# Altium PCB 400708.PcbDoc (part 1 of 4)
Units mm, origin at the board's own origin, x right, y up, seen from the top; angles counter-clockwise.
Board outline 117 x 63.5 mm, 4 copper layers (Top Layer, Mid-Layer 1, Mid-Layer 2, Bottom Layer), stack 1.556 mm thick; 207 components, 162 nets, 822 pads, 1266 vias.
Unrouted connection lines stored in the file: 43.
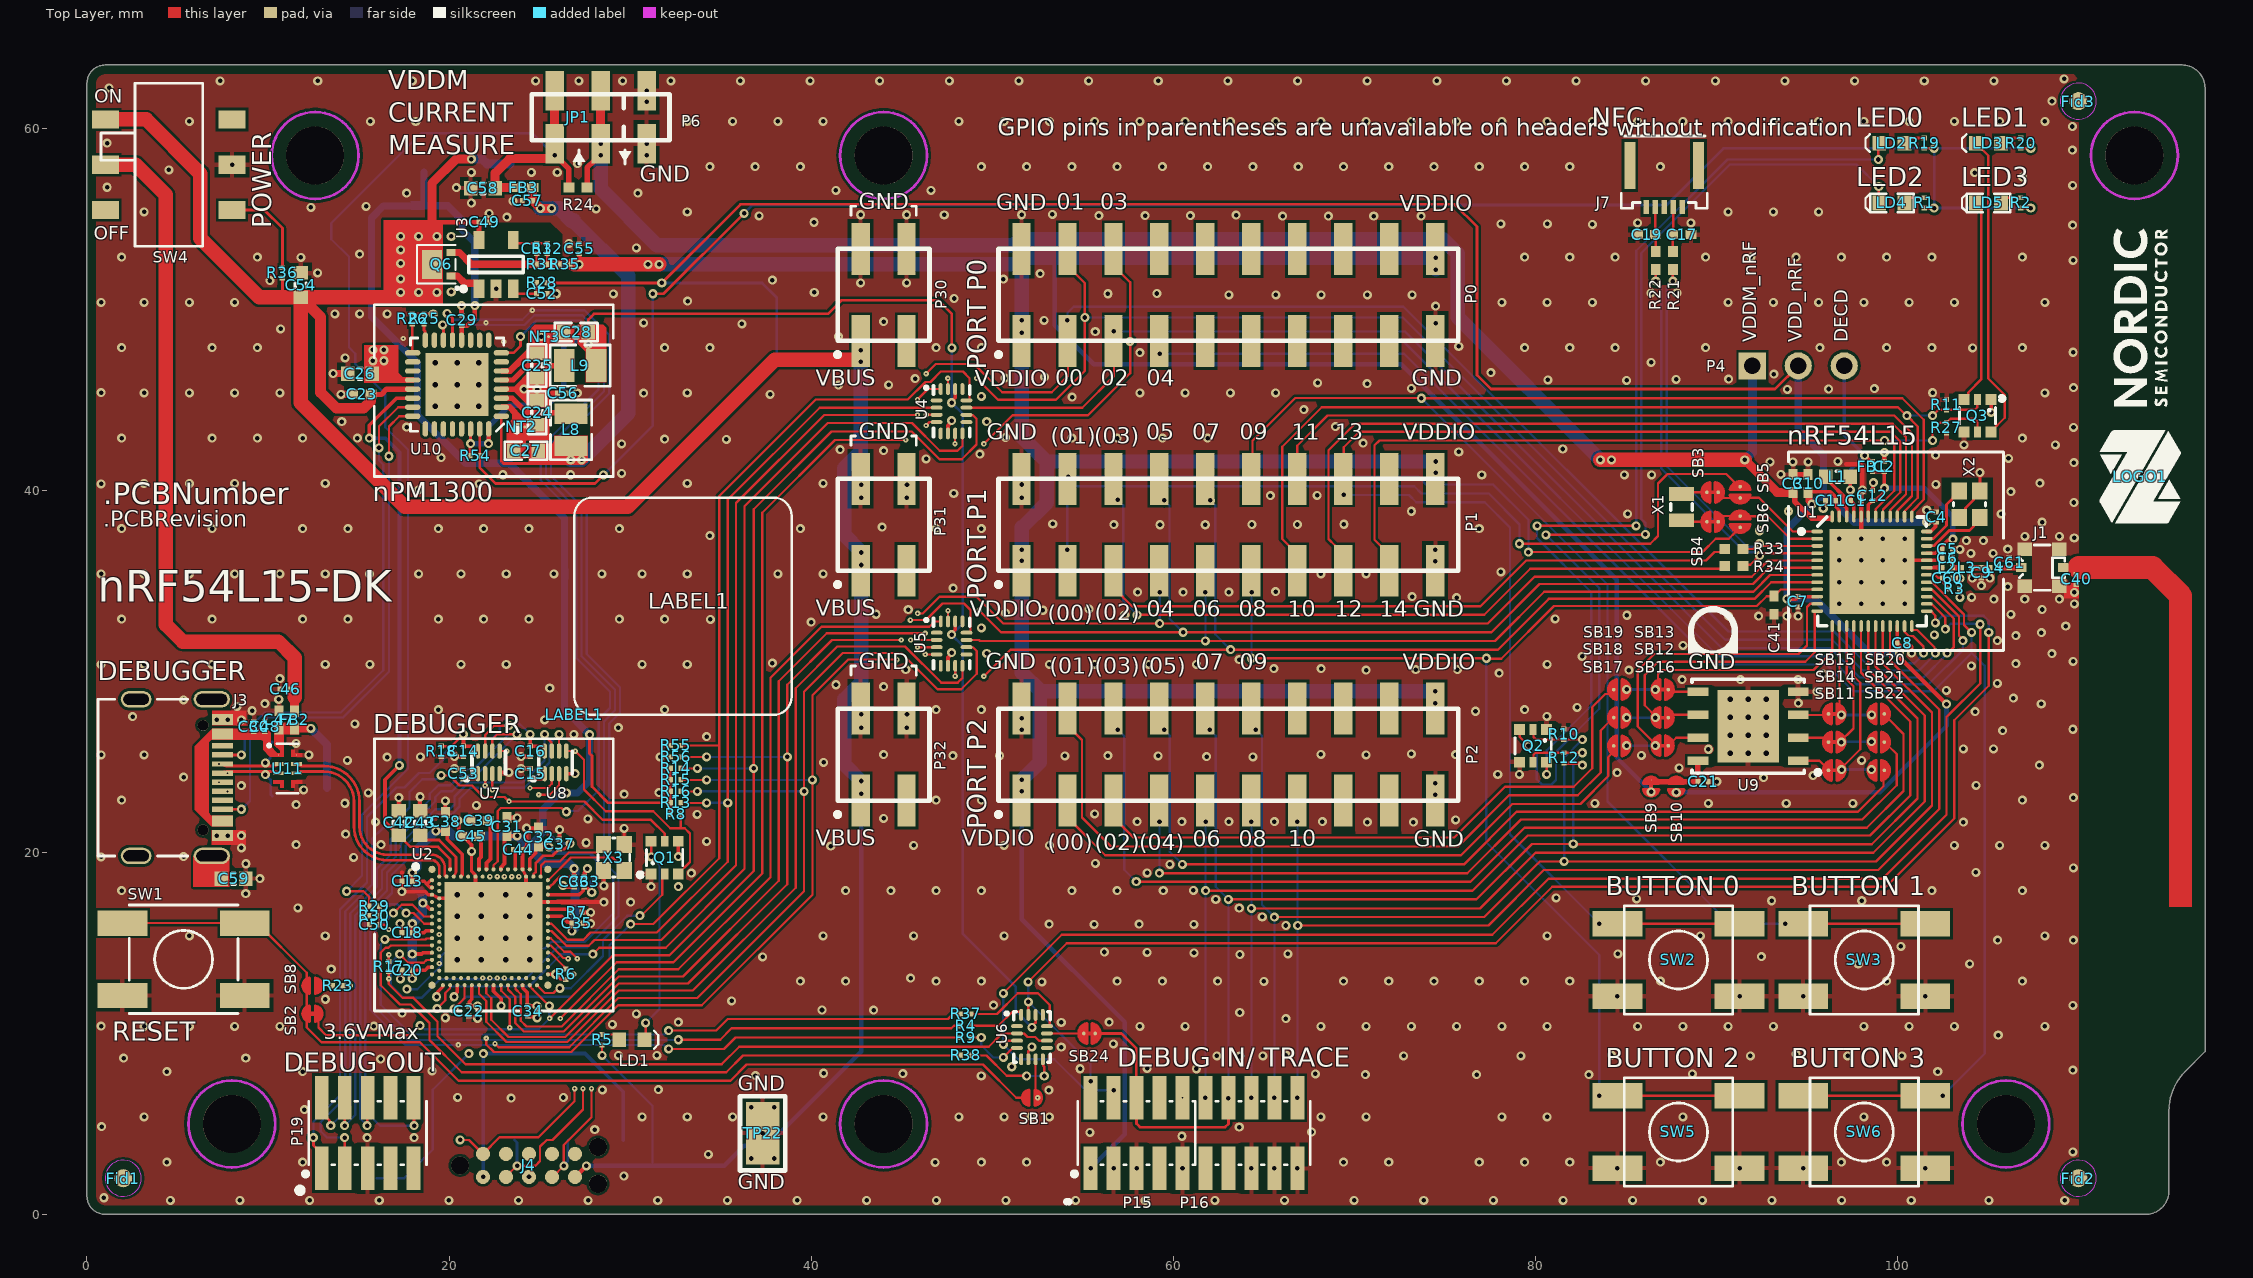
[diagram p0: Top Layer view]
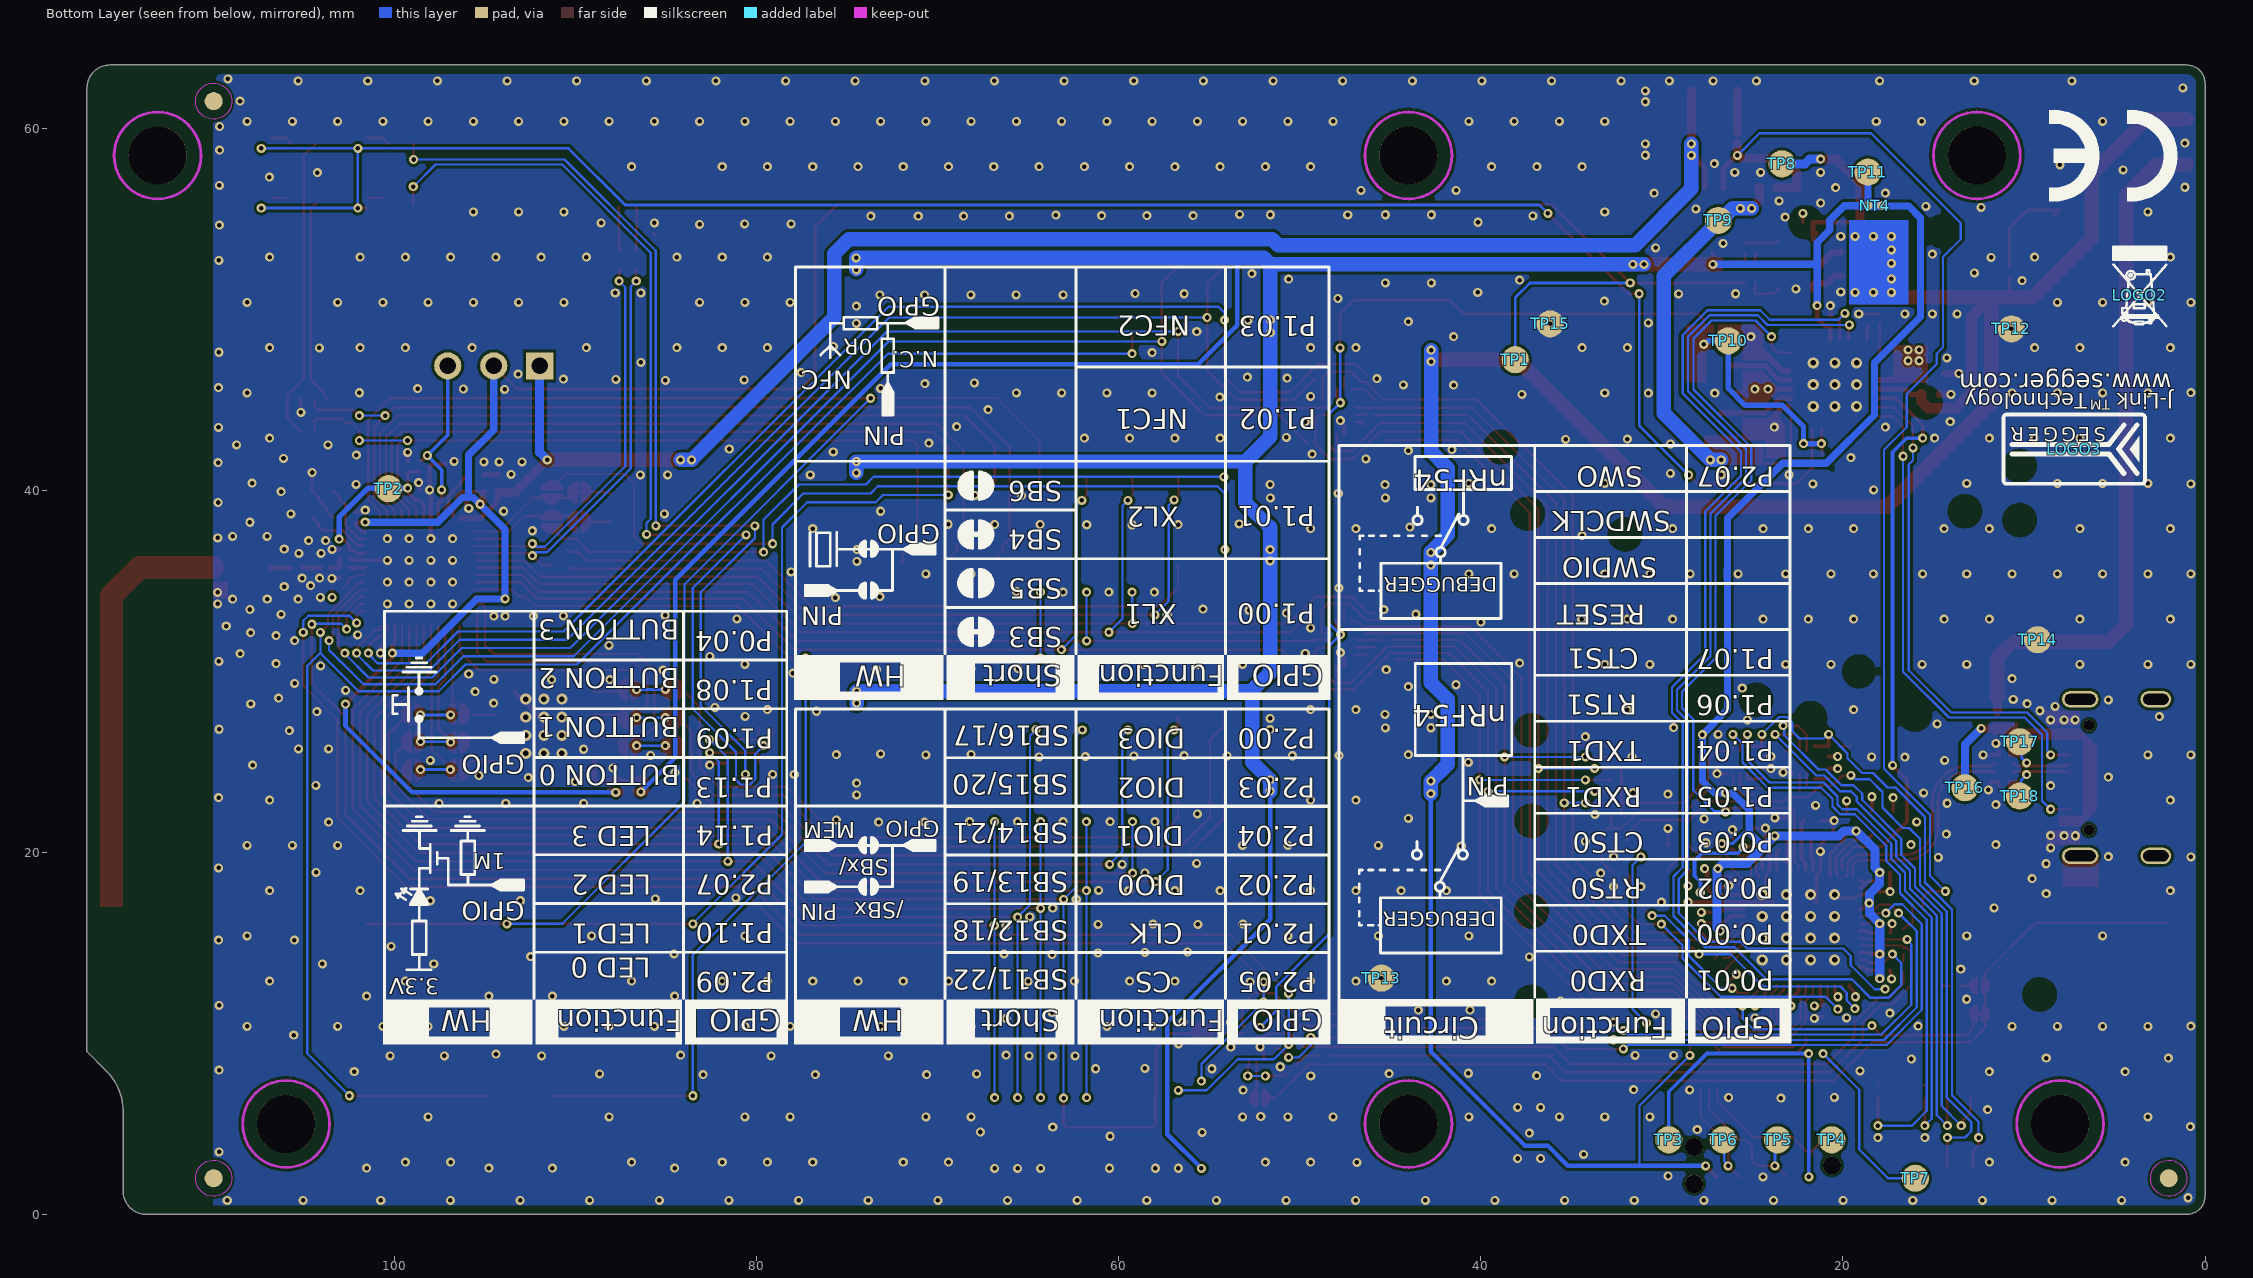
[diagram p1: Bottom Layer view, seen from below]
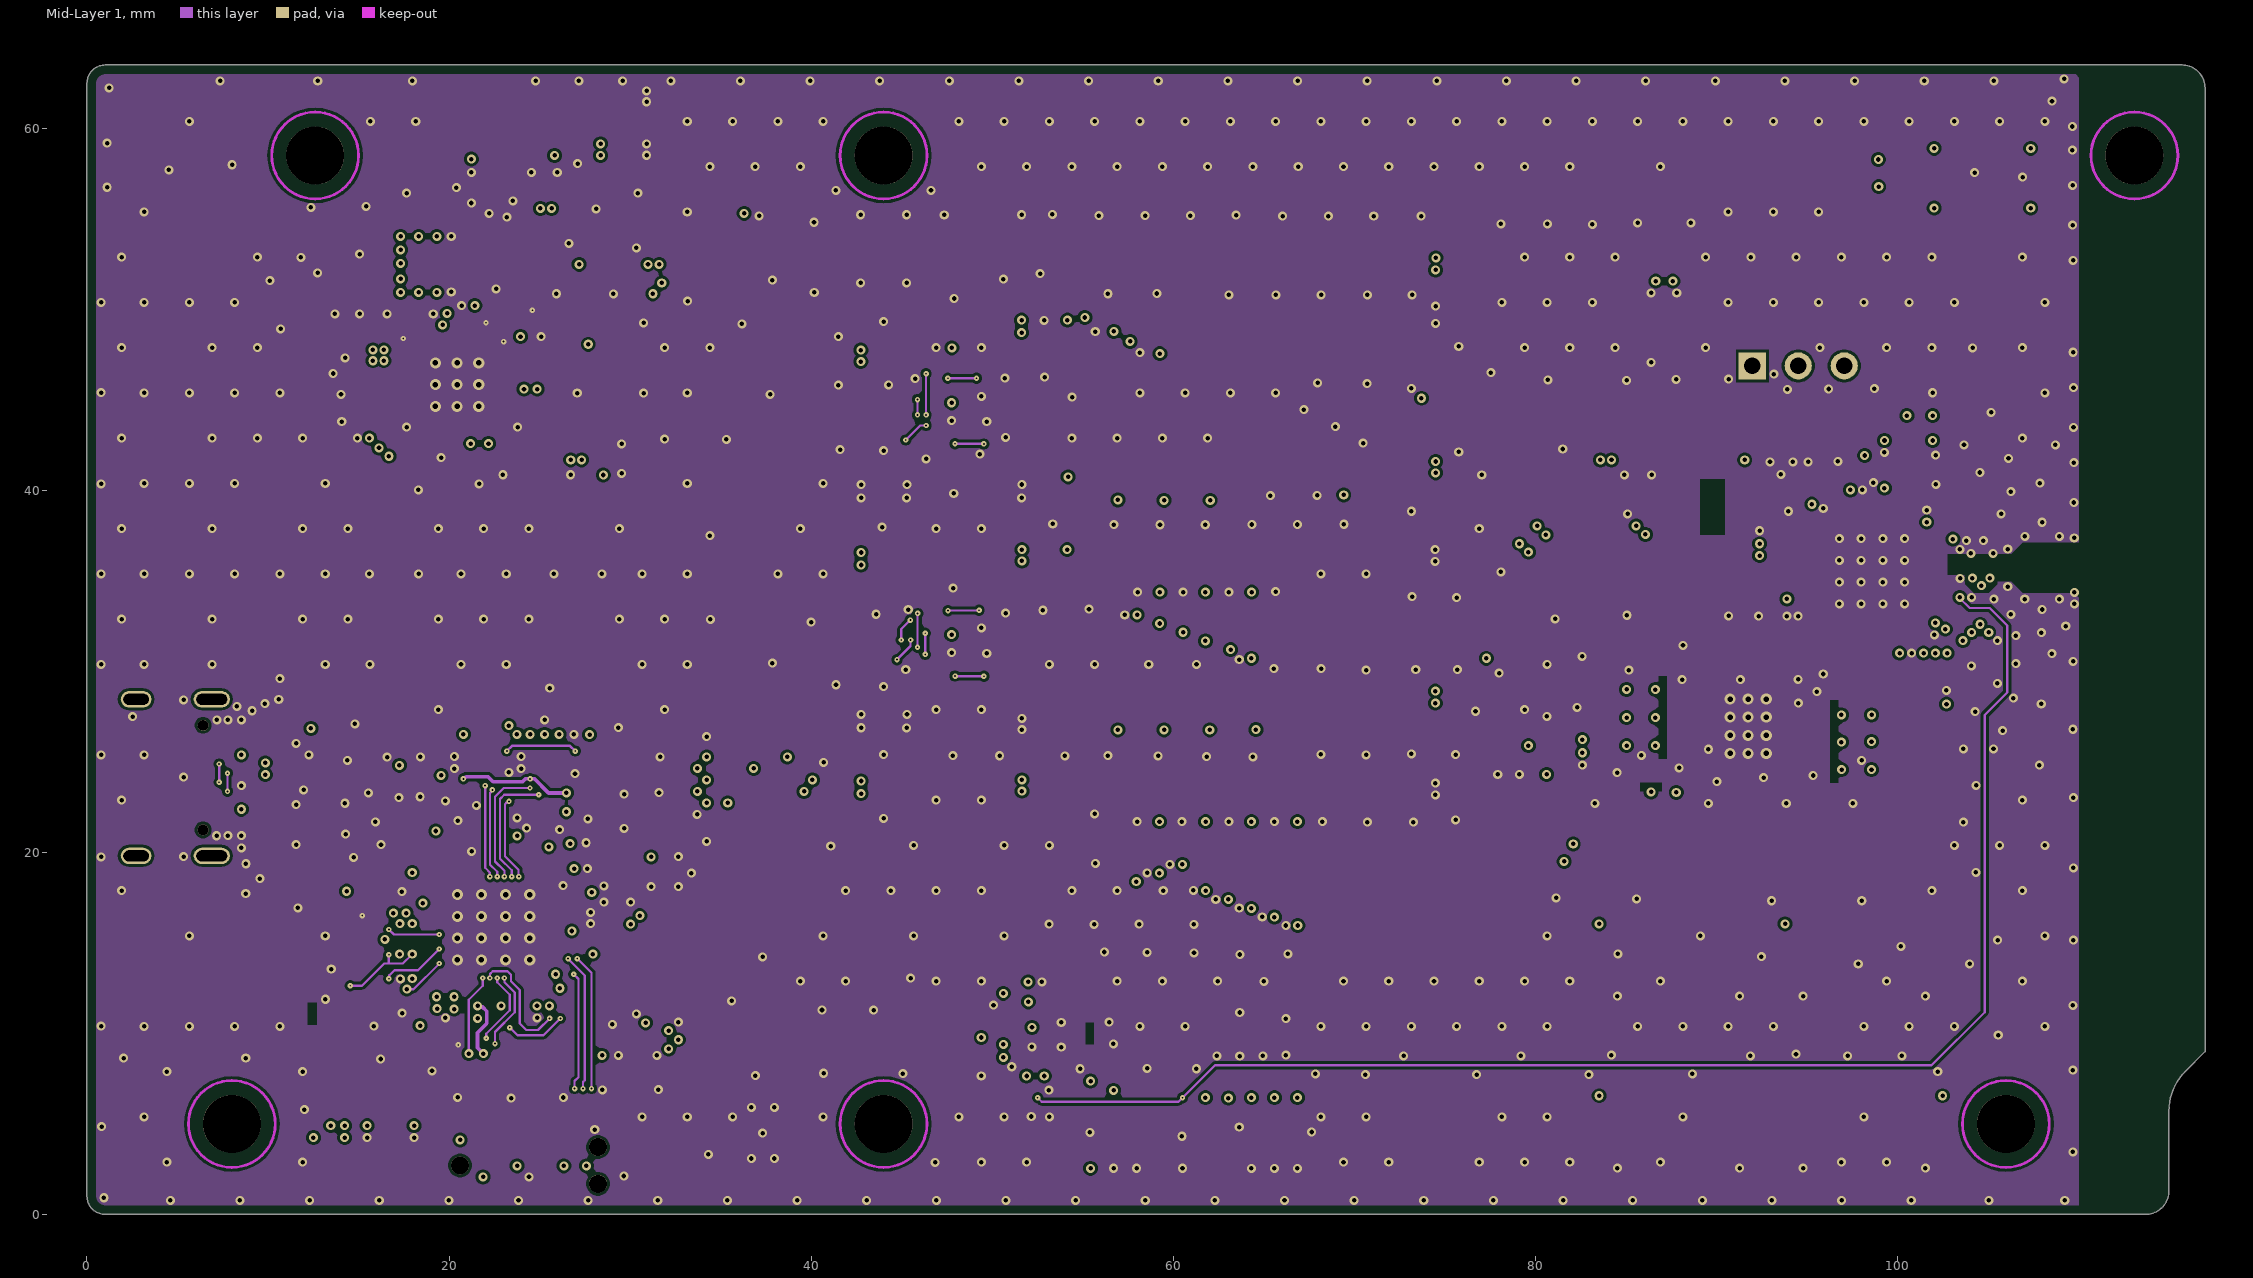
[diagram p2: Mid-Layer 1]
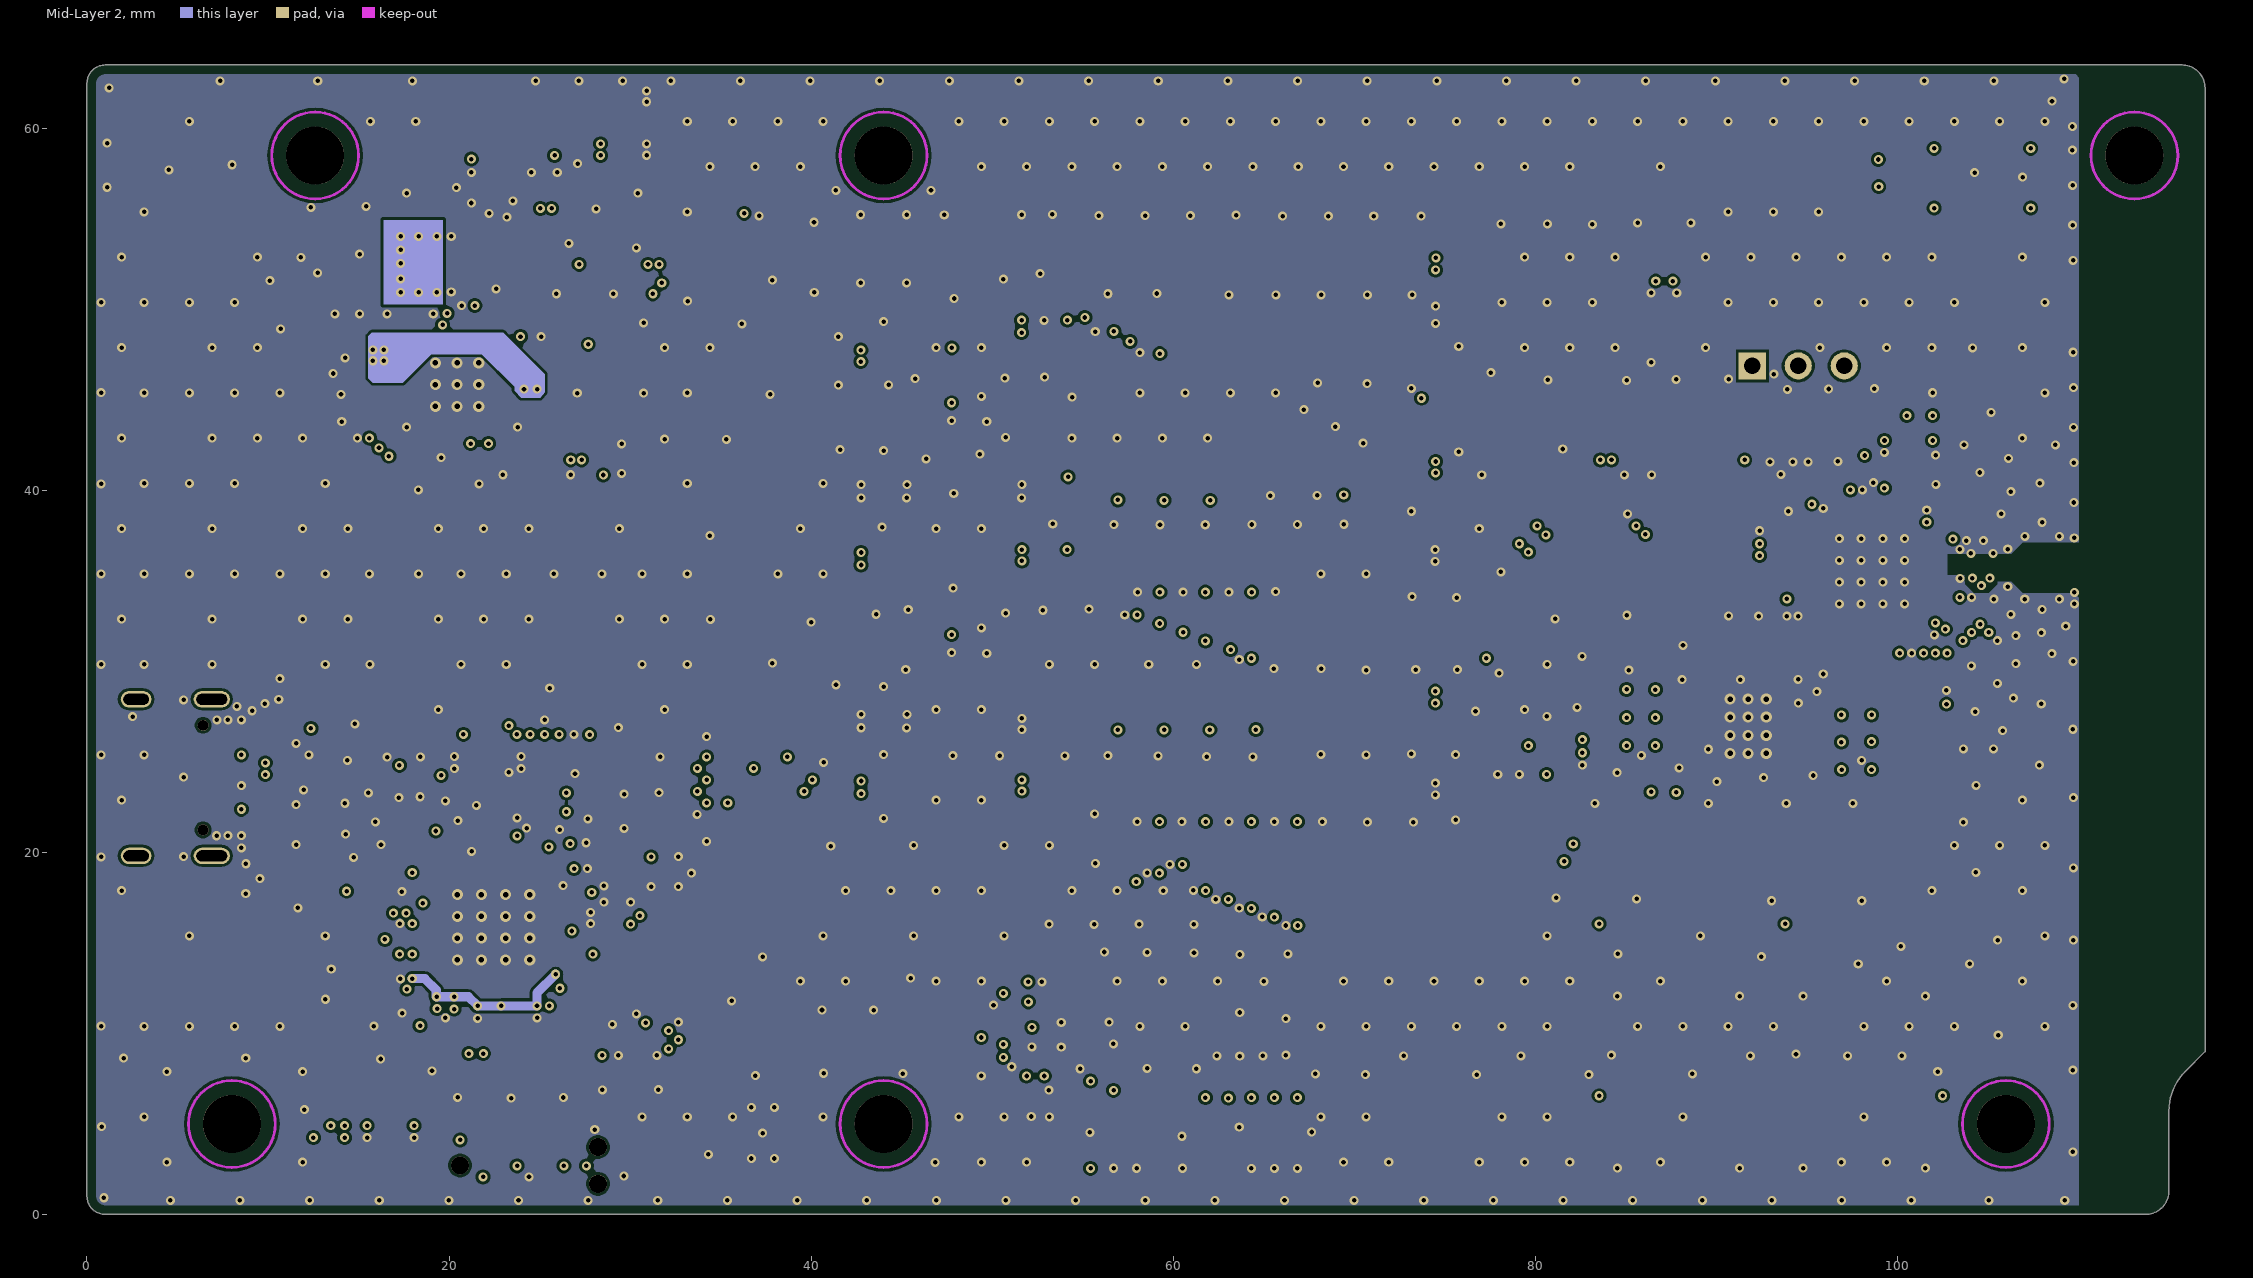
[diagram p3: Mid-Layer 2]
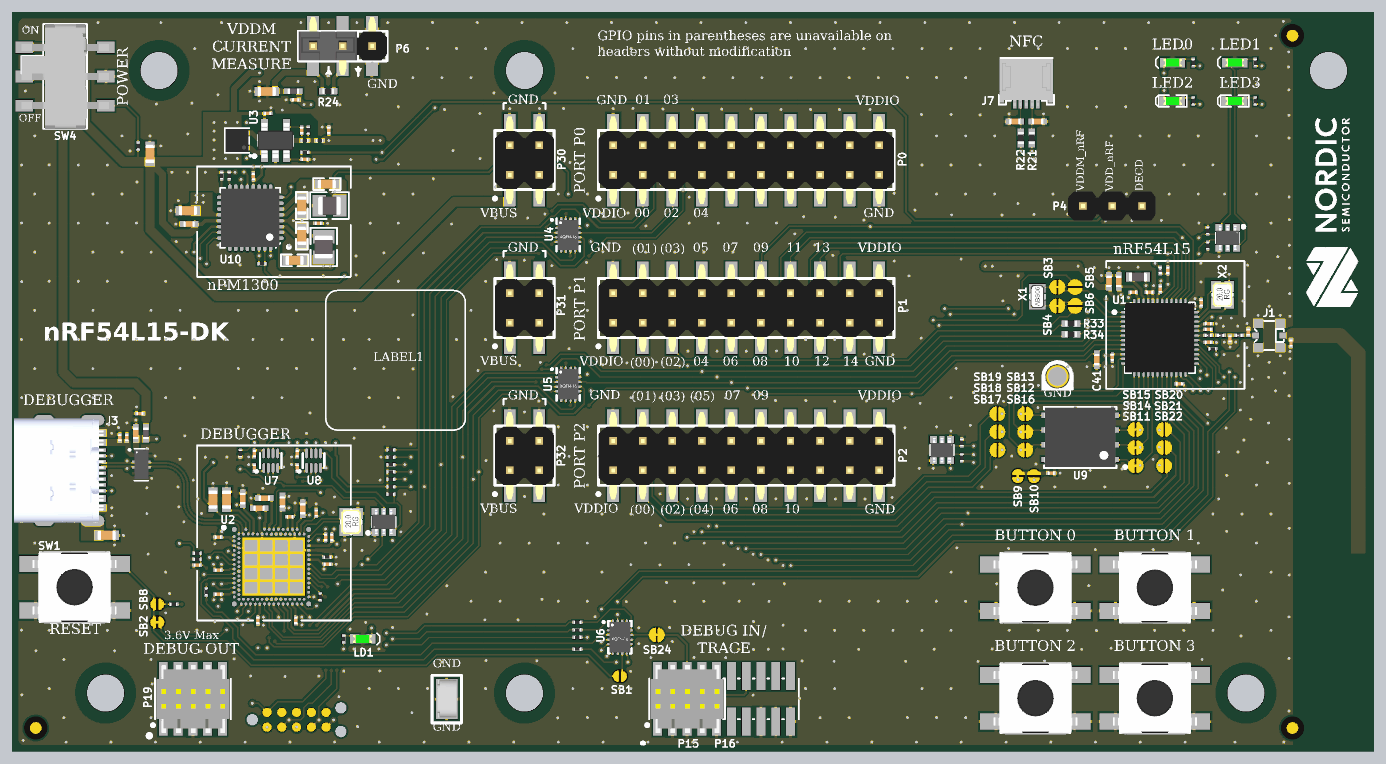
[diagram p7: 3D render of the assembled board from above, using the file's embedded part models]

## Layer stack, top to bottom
Top Solder: solder mask 0.0102, Solder Resist, Dk 3.5
Top Layer: signal copper 0.048
Dielectric 1: prepreg 0.1, PP-021, Dk 4.2
Mid-Layer 1: signal copper 0.03
Dielectric 2: core 1.2, Core-042, Dk 4.2
Mid-Layer 2: signal copper 0.03
Dielectric 3: prepreg 0.1, PP-021, Dk 4.2
Bottom Layer: signal copper 0.048
Bottom Solder: solder mask 0.0102, Solder Resist, Dk 3.5

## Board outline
1.016,0 cw(c1.016,1.016) 0,1.016 0,62.484 cw(c1.016,62.484) 1.016,63.5 115.734,63.5 cw(c115.734,62.23) 117.004,62.23 117.004,9 115.92,7.916 ccw(c118.132,5.705) 115.004,5.705 115.004,1.295 cw(c113.709,1.295) 113.709,0

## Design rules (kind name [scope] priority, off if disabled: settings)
AssemblyTestPointUsage [All] p1 off:
AssemblyTestpoint [All] p1 off: testpointundercomponent=TRUE minsize=1.016 maxsize=2.54 preferedsize=1.524 minholesize=0 maxholesize=1.016 preferedholesize=0.813 testpointgrid=0.025 usegrid=TRUE gridtolerance=0 allowsidetop=TRUE allowsidebottom=TRUE
BoardOutlineClearance [All] p1: gap=0.508 ignorepadtopadclearanceinfootprint=FALSE except(0: Arc-SplitContinuation Track-SplitContinuation SMDPad-SplitContinuation THPad-SplitContinuation Via-SplitContinuation Fill-SplitContinuation Poly-SplitContinuation Region-SplitContinuation Text-SplitContinuation)
Clearance ANT_Clearance [InNet('ANT') or InNet('RF') or InNet('NetC9_2') or InNet('NetC6_2')] p1: gap=0.16 ignorepadtopadclearanceinfootprint=FALSE
Clearance Polygon_Clearance [(InNamedPolygon('Mid_Layer1-GND')) or (InNamedPolygon('Bottom_Layer-GND')) or (InNamedPolygon('Mid_Layer2-GND')) or (InNamedPolygon('Top_Layer-GND'))] p2: gap=0.15 ignorepadtopadclearanceinfootprint=FALSE
Clearance Clearance_IMCU [WithinRoom('nRF5340')] p3: gap=0.1 ignorepadtopadclearanceinfootprint=FALSE
Clearance DiffPair_Clearance [InNetClass('IMCU_USB')] p4: gap=0.127 ignorepadtopadclearanceinfootprint=FALSE
Clearance [All] p5: gap=0.15 ignorepadtopadclearanceinfootprint=FALSE except(0.25: THPad-Region)
ComponentClearance [All] p1 off: gap=0.254 collisioncheckmode=3 verticalgap=0.254 showdistances=FALSE
DiffPairsRouting [InDifferentialPairClass('All Differential Pairs')] p1: maxlimit=0.15 minlimit=0.15 mostfreqgap=0.15 toplayer_minwidth=0.125 toplayer_maxwidth=0.153 toplayer_prefwidth=0.153 midlayer1_minwidth=0.125 midlayer1_maxwidth=0.153 midlayer1_prefwidth=0.125 midlayer4_minwidth=0.125 midlayer4_maxwidth=0.153 midlayer4_prefwidth=0.125 bottomlayer_minwidth=0.125 bottomlayer_maxwidth=0.153 bottomlayer_prefwidth=0.153 maxuncoupledlength=10
FabricationTestPointUsage TestPointUsage [All] p1 off: valid=2 allowmultiple=FALSE
FabricationTestpoint Testpoint [All] p1 off: side=2 testpointundercomponent=TRUE minsize=1.016 maxsize=2.54 preferedsize=1.524 minholesize=0 maxholesize=1.016 preferedholesize=0.813 testpointgrid=2.54 allowsidebottom=TRUE usegrid=TRUE gridtolerance=0
Height [All] p1 off: minheight=0 maxheight=25.4 prefheight=12.7
HoleSize [All] p1: absolutevalues=TRUE maxlimit=5 minlimit=0.1 maxpercent=80.000 minpercent=20.000
HoleToHoleClearance [IsThruVia] p1: gap=0.35 allowstackedmicrovias=FALSE
LayerPairs [All] p1 off: enforce=TRUE
MatchedLengths "Schematic Matched Net Lengths" [InNetClass('TRACE')] p1: tolerance=25.4 checknetsindiffpair=FALSE checkdiffpairvsdiffpair=TRUE checkxsignals=TRUE checkothers=TRUE usedelayunits=TRUE delaytolerance=500.000000
MatchedLengths MatchedLengths-Diffpairs [InDifferentialPairClass('All Differential Pairs')] p2: tolerance=1.27 checknetsindiffpair=TRUE checkdiffpairvsdiffpair=FALSE checkxsignals=FALSE checkothers=FALSE
MinimumAnnularRing [All] p1 off: minimumring=0.1
MinimumSolderMaskSliver [All] p1: minsoldermaskwidth=0.1
NetAntennae [All] p1 off: netantennaetolerance=0.3
PolygonConnect PolygonConnect_TP [HasFootprint('TP_SMD_D1.5mm') vs InNet('GND')] p1: connectstyle=Direct reliefconductorwidth=0.254 reliefentries=4 polygonreliefangle="90 Angle" airgapwidth=0.254
PolygonConnect PolygonConnect_SMT_Pads [HasFootprint('COAXIAL-SWF') or InComponent('C9') or InComponent('C61') vs InNet('GND')] p2: connectstyle=Direct reliefconductorwidth=0.254 reliefentries=4 polygonreliefangle="90 Angle" airgapwidth=0.254
PolygonConnect [All] p3: thpad.connectstyle=Relief thpad.reliefconductorwidth=0.254 thpad.reliefentries=4 thpad.polygonreliefangle="90 Angle" thpad.airgapwidth=0.2 smdpad.connectstyle=Relief smdpad.reliefconductorwidth=0.254 smdpad.reliefentries=4 smdpad.polygonreliefangle="90 Angle" smdpad.airgapwidth=0.2 via.connectstyle=Direct via.reliefconductorwidth=0.254 via.reliefentries=4 via.polygonreliefangle="90 Angle" via.airgapwidth=0.254
RoutingVias RoutingVias_Blind [IsBlindVia or IsMicroVia] p1: holewidth=0.711 width=1.27 viastyle="Through Hole" minholewidth=0.711 minwidth=1.27 maxholewidth=0.711 maxwidth=1.27 useviatemplates=TRUE viatemplateguid#1={B6F7EE11-84B8-42C4-BDC0-4B8B407402DD} viatemplatename#1=v30h10m0
RoutingVias RoutingVias_thru [IsThruVia] p2: holewidth=0.305 width=0.61 viastyle="Through Hole" minholewidth=0.305 minwidth=0.61 maxholewidth=0.711 maxwidth=1.27 useviatemplates=TRUE viatemplateguid#1={462064FF-42C7-473E-A651-561C1576AFDF} viatemplateguid#2={99171295-E844-4990-BFE5-753CC0A313CB} viatemplateguid#3={DB312F71-B2A7-4ABA-8448-376194653462} viatemplateguid#4={E2A9C569-A2DE-41A1-8420-4C4C8AB4608D} viatemplatename#1=v50h25m0mx0 viatemplatename#2=v50h25m0mx0(1) viatemplatename#3=v61h30 viatemplatename#4=v61h30m0mx0
ShortCircuit ShortCircuit_P15_P16 [InComponent('P15') vs InComponent('P16')] p1: allowed=TRUE
ShortCircuit ShortCircuit_PSS [InNet('PVSS1') or InNet('PVSS2') vs InNet('GND')] p2: allowed=TRUE
ShortCircuit [All] p3: allowed=FALSE
SilkToSilkClearance [All] p1 off: silktosilkclearance=0.254
SilkToSolderMaskClearance SilkscreenOverComponentPads [IsPad] p1 off: minsilkscreentomaskgap=0.254 clearancetoexposedcopper=TRUE
SolderMaskExpansion SolderMaskExpansion_XFDFN40 [HasFootprint('XFDFN40P180X120X40-8M')] p1: expansion=0.02 istentingtop=FALSE
SolderMaskExpansion SolderMaskExpansion_footprints [HasFootprint('UDFN65P200X200X60_HS-6N') or HasFootprint('SON50P300X80-HS-11N') or HasFootprint('US8') or HasFootprint('SON50P300X80_HS-9N') or HasFootprint('BGA25C40P5X5_200X200X50') or HasFootprint('QFN40P180X140X55-10N') or HasFootprint('DX07S016JA1R1500') or HasFootprint('AQFN40P700X700X85_HS-99N') or HasFootprint('Nordic_QFN50P500X500X90-33N')] p2: expansion=0.03 istentingtop=FALSE
SolderMaskExpansion SolderMaskExpansion_VIA [IsVia] p3: expansion=0.076 istentingtop=TRUE
SolderMaskExpansion [All] p4: expansion=0.05 istentingtop=FALSE
SupplyNets "Schematic Supply Nets_12" [InNet('P5V0')] p1: voltage=0.000
SupplyNets "Schematic Supply Nets_11" [InNet('GND')] p2: voltage=0.000
SupplyNets "Schematic Supply Nets_10" [InNet('VDDM_nRF')] p3: voltage=0.000
SupplyNets "Schematic Supply Nets_9" [InNet('VDDIO')] p4: voltage=0.000
SupplyNets "Schematic Supply Nets_8" [InNet('VDD_SWD0')] p5: voltage=0.000
SupplyNets "Schematic Supply Nets_7" [InNet('P3V3')] p6: voltage=0.000
SupplyNets "Schematic Supply Nets_6" [InNet('VDD_nRF')] p7: voltage=0.000
SupplyNets "Schematic Supply Nets_5" [InNet('VDD_DBGR')] p8: voltage=0.000
SupplyNets "Schematic Supply Nets_4" [InNet('PVSS2')] p9: voltage=0.000
SupplyNets "Schematic Supply Nets_3" [InNet('PVSS1')] p10: voltage=0.000
SupplyNets "Schematic Supply Nets_2" [InNet('VBUSOUT')] p11: voltage=0.000
SupplyNets "Schematic Supply Nets_1" [InNet('VDDM')] p12: voltage=0.000
SupplyNets "Schematic Supply Nets" [InNet('VBUS')] p13: voltage=0.000
Width Width_IMCU [OnTopLayer and HasFootprint('BGA144C35P12X12_450X420X100-A8-M3')] p1: maxlimit=2.5 minlimit=0.1 preferedwidth=0.15
Width [All] p2: maxlimit=2.5 minlimit=0.125 preferedwidth=0.15
15 further rules are at their usual default settings.

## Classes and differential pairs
differential pair class IMCU: DBGR DBGR'
net class TRACE: P2.06 P2.07 P2.08 P2.09 P2.10
net class IMCU_USB: DBGR'_N DBGR'_P DBGR_N DBGR_P
component class "Power supply": C23 C24 C25 C26 C27 C28 C29 C49 C51 C52 C55 C56 C57 C58 FB3 JP1 L8 L9 NT2 NT3 P6 Q6 R24 R25 R26 R28 R31 R32 R35 R54 TP8 TP9 TP10 TP11 TP12 TP13 TP14 TP15 U3 U10
component class "Levelshifters and switches": C14 C15 C16 C53 R8 R13 R14 R15 R16 R17 R18 R55 R56 SB24 U4 U5 U6 U7 U8
component class nRF54L15: C1 C2 C3 C4 C5 C6 C7 C8 C9 C10 C11 C12 C40 C41 C60 C61 FB1 J1 L1 L2 L3 L4 P4 R3 R33 R34 SB3 SB4 SB5 SB6 SB11 SB12 SB13 SB14 SB15 SB16 SB17 SB18 SB19 SB20 SB21 SB22 TP1 TP2 U1 X1 X2
component class Debugger: C13 C18 C20 C22 C31 C32 C33 C34 C35 C36 C37 C38 C39 C42 C43 C44 C45 C50 J4 LD1 NT4 Q1 R4 R5 R6 R7 R9 R29 R30 R37 R38 TP3 TP4 TP5 TP6 TP7 U2 X3
component class Misc: C17 C19 C21 LD2 LD3 LD4 LD5 Q2 Q3 R1 R2 R10 R11 R12 R19 R20 R21 R22 R23 R27 SB8 SB9 SB10 SW1 SW2 SW3 SW5 SW6 U9
component class Connectors: C30 C46 C47 C48 C54 C59 FB2 J3 J7 P0 P1 P2 P15 P16 P19 P30 P31 P32 R36 SW4 TP16 TP17 TP18 TP22 U11
component class pca10156_sheet1_connections: Fid1 Fid2 Fid3 LABEL1 LOGO1 LOGO2 LOGO3 SB1 SB2
differential pair DBGR: +DBGR_P -DBGR_N
differential pair DBGR': +DBGR'_P -DBGR'_N

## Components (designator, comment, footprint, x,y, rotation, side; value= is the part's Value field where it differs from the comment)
C1 "2.2µF" CAPC0603X03L_C 97.72,39.439 r180 top
C2 "2.2µF" CAPC0603X03L_C 99.294,41.317 r270 top
C3 "10µF" CAPC1005X04L 94.239,40.377 r270 top
C4 "100nF" CAPC0603X03L_C 102.164,38.523 r90 top
C5 "2.2nF" CAPC0603X03L_C 102.773,36.75 r180 top
C6 "1.5pF" CAPC0603X03L_C 102.773,36.25 r0 top
C7 "100nF" CAPC0603X03L_C 94.518,33.849 r270 top
C8 "100nF" CAPC0603X03L_C 100.284,31.568 r0 top
C9 "2.0pF" CAPC0603X03L_C 104.635,35.445 r90 top
C10 "10µF" CAPC1005X04L 95.077,40.377 r270 top
C11 "100nF" CAPC0603X03L_C 96.322,39.437 r180 top
C12 "10nF" CAPC0603X03L_C 98.633,39.717 r90 top
C13 "100nF" CAPC0603X03L_C 17.689,18.401 r180 top
C14 "100nF" CAPC0603X03L_C 20.798,25.585 r270 top
C15 "100nF" CAPC0603X03L_C 24.481,24.349 r270 top
C16 "100nF" CAPC0603X03L_C 24.481,25.585 r270 top
C17 "300pF" CAPC1005X04L 88.104,54.123 r0 top
C18 "100nF" CAPC0603X03L_C 17.689,15.573 r180 top
C19 "300pF" CAPC1005X04L 86.152,54.123 r0 top
C20 "100nF" CAPC0603X03L_C 17.689,13.499 r180 top
C21 "100nF" CAPC0603X03L_C 89.275,23.902 r0 top
C22 "100nF" CAPC0603X03L_C 21.092,11.239 r270 top
C23 "2.2µF" CAPC1005X04L 15.184,45.313 r0 top
C24 "10µF" CAPC1608X06L 24.867,44.296 r90 top locked
C25 "10µF" CAPC1608X06L 24.867,46.896 r270 top locked
C26 "10µF" CAPC1608X06L 15.082,46.456 r0 top
C27 "10µF" CAPC1608X06L 24.249,42.186 r0 top locked
C28 "10µF" CAPC1608X06L 27.02,48.742 r0 top locked
C29 "100nF" CAPC0603X03L_C 20.699,49.386 r90 top
C30 "10nF" CAPC0603X03L_C 9.225,26.95 r90 top
C31 "1.0µF" CAPC1005X04L 23.2,21.424 r90 top
C32 "1.0µF" CAPC1005X04L 24.953,20.84 r270 top
C33 "2.2nF" CAPC0603X03L_C 27.459,18.376 r90 top
C34 "100nF" CAPC0603X03L_C 24.343,11.239 r270 top
C35 "100nF" CAPC0603X03L_C 27.068,16.078 r0 top
C36 "100nF" CAPC0603X03L_C 26.909,18.376 r270 top
C37 "100nF" CAPC0603X03L_C 26.096,20.459 r90 top
C38 "1.0µF" CAPC1005X04L 19.797,21.703 r270 top
C39 "1.0µF" CAPC1005X04L 21.651,21.754 r0 top
C40 "1.4pF" CAPC0603X03L_C 109.88,35.08 r90 top
C41 "100nF" CAPC1005X04L 93.186,33.655 r90 top
C42 "4.7µF" CAPC1608X06L 17.231,21.627 r90 top
C43 "4.7µF" CAPC1608X06L 18.4,21.627 r90 top
C44 "100nF" CAPC0603X03L_C 23.835,20.154 r0 top
C45 "1.0µF" CAPC1005X04L 21.194,20.891 r0 top
C46 "100nF" CAPC0603X03L_C 10.95,29.025 r0 top
C47 "1.0µF" CAPC1005X04L 10.6,27.325 r270 top
C48 "100nF" CAPC0603X03L_C 9.825,26.95 r270 top
C49 "100nF" CAPC0603X03L_C 21.934,54.811 r0 top
C50 "10nF" CAPC0603X03L_C 15.879,16.002 r180 top
C51 "TBD" CAPC0603X03L_C 24.849,53.361 r270 top
C52 "100nF" CAPC0603X03L_C 25.124,50.861 r0 top
C53 "100nF" CAPC0603X03L_C 20.798,24.349 r270 top
C54 "4.7µF" CAPC1608X06L 11.815,51.336 r90 top
C55 "100nF" CAPC0603X03L_C 27.187,53.361 r90 top
C56 "100nF" CAPC0603X03L_C 26.286,45.365 r180 top
C57 "100nF" CAPC0603X03L_C 24.332,55.988 r0 top
C58 "4.7µF" CAPC1608X06L 21.869,56.7 r180 top
C59 "10nF" CAPC1608X06L 8.1,18.552 r0 top
C60 "3.9pF" CAPC0603X03L_C 102.773,35.149 r0 top
C61 "0.3pF" CAPC0603X03L_C 106.2,36.015 r270 top
FB1 "120R/0.2A" INDC0603X03L_C 98.633,41.317 r270 top
FB2 "120R/0.55A" INDC1005X04L 11.475,27.325 r90 top
FB3 "120R/0.55A" INDC1005X04L 24.142,56.725 r180 top
Fid1 "Fiducial mark" Fiducial 2.004,2 r0 top value=N.A.
Fid2 "Fiducial mark" Fiducial 110.004,2 r0 top locked value=N.A.
Fid3 "Fiducial mark" Fiducial 110.004,61.5 r0 top locked value=N.A.
J1 "MM8130-2600" COAXIAL-SWF 108.005,35.73 r90 top locked
J3 "USB-C 2.0" SD-80259-001 5.1,24.134 r270 top locked
J4 "TC2050-IDC" TC2050-IDC-NLFP 24.418,2.709 r0 top locked
J7 "FPC 0.5mm RA SMD" FPC_05P-0.5mm-RA-SMD 88.129,55.654 r180 top locked
JP1 "Shunt 2.54mm" Shunt_2.54mm_Vertical 27.113,60.625 r180 top
L1 "4.7µH" INDC1608X06L 96.728,40.758 r180 top
L2 "2.7nH" INDC0603X03L_C 102.773,35.73 r0 top
L3 "3.5nH" INDC0603X03L_C 103.83,35.73 r0 top
L4 "3.5nH" INDC0603X03L_C 105.406,35.73 r0 top
L8 "2.2µH" INDC2016X10N 26.749,43.336 r90 top locked
L9 "2.2µH" INDC2016X10N 27.249,46.887 r180 top locked
LABEL1 "12x12mm" LabelSilk_12x12 26.925,27.6 r0 top
LD1 "L0603G" LED_0603_G 30.103,9.652 r180 top
LD2 "L0603G" LED_0603_G 99.709,59.182 r0 top
LD3 "L0603G" LED_0603_G 105.043,59.182 r0 top
LD4 "L0603G" LED_0603_G 99.709,55.88 r0 top locked
LD5 "L0603G" LED_0603_G 105.043,55.88 r0 top locked
LOGO1 "Nordic Logo" NORDIC_LOGO_LYING 113.429,40.75 r90 top
LOGO2 "WEE Symbol" WEE_3x4.5mm 3.6,50.775 r0 bottom
LOGO3 "Segger Logo S" SEGGER_LOGO_S 7.225,42.275 r0 bottom
NT2 "Net tie" "2 PIN STARPOINT" 23.983,43.502 r180 top net-tie
NT3 "Net tie" "2 PIN STARPOINT" 25.295,48.496 r180 top net-tie
NT4 "N.A." "2 pin starpoint 20mil" 18.241,55.733 r180 bottom net-tie
P0 "Pin Hdr 2x10" HDR_2x10-SMD 63.054,50.8 r0 top locked
P1 "Pin Hdr 2x10" HDR_2x10-SMD 63.054,38.1 r0 top locked
P2 "Pin Hdr 2x10" HDR_2x10-SMD 63.054,25.4 r0 top locked
P4 "Pin List 1x3" LIST_1x3 94.535,46.88 r0 top locked
P6 "Pin List 1x3" LIST_1x3_SMD 30.912,60.606 r180 top locked
P15 "Pin Header 2x5, 1.27mm" HDR_2x5-SMD-1.27mm-K 57.978,4.5 r0 top locked
P16 "Pin Header 2x10, 1.27mm" HDR_2x10-SMD-1.27mm-NC 61.153,4.5 r0 top locked
P19 "Pin Header 2x5, 1.27mm" HDR_2x5-SMD-1.27mm-K 15.504,4.5 r0 top locked
P30 "Pin Header 2x2 SMD" HDR_2x2-SMD 44.004,50.8 r0 top locked
P31 "Pin Header 2x2 SMD" HDR_2x2-SMD 44.004,38.1 r0 top locked
P32 "Pin Header 2x2 SMD" HDR_2x2-SMD 44.004,25.4 r0 top locked
Q1 "NX138AKS" TSSOP6 31.915,19.715 r0 top
Q2 "NX138AKS" TSSOP6 79.884,25.885 r180 top
Q3 "NX138AKS" TSSOP6 104.435,44.13 r180 top
Q6 "PBSS4330PA" DFN105P200X65-3N_v2 19.299,52.486 r180 top locked
R1 "220R" RESC0603X03L_C 101.487,55.88 r270 top
R2 "220R" RESC0603X03L_C 106.821,55.88 r270 top
R3 "0R" RESC0603X03L_C 103.15,34.575 r0 top
R4 "150R" RESC0603X03L_C 48.55,10.425 r0 top
R5 "560R" RESC0603X03L_C 28.452,9.652 r270 top
R6 "100k" RESC0603X03L_C 26.46,13.271 r270 top
R7 "47R" RESC0603X03L_C 27.06,16.687 r0 top
R8 "100k" RESC0603X03L_C 32.516,22.098 r180 top
R9 "150R" RESC0603X03L_C 48.55,9.776 r0 top
R10 "1M0" RESC0603X03L_C 81.585,26.524 r90 top
R11 "1M0" RESC0603X03L_C 102.723,44.734 r90 top
R12 "1M0" RESC0603X03L_C 81.592,25.221 r270 top
R13 "100k" RESC0603X03L_C 32.516,22.733 r0 top
R14 "100k" RESC0603X03L_C 32.516,24.638 r0 top
R15 "100k" RESC0603X03L_C 32.516,24.003 r0 top
R16 "100k" RESC0603X03L_C 32.516,23.368 r0 top
R17 "100k" RESC0603X03L_C 16.668,13.696 r270 top
R18 "1M0" RESC0603X03L_C 19.573,25.585 r90 top
R19 "220R" RESC0603X03L_C 101.487,59.182 r270 top
R20 "220R" RESC0603X03L_C 106.821,59.182 r270 top
R21 "0R" RESC1005X04L 87.604,52.704 r90 top
R22 "0R" RESC1005X04L 86.661,52.704 r90 top
R23 "100k" RESC0603X03L_C 13.854,12.634 r0 top
R24 "TBD" RESC1005X04L 27.125,56.725 r180 top
R25 "270k" RESC0603X03L_C 18.619,49.468 r90 top
R26 "47k" RESC0603X03L_C 17.973,49.468 r90 top
R27 "1M0" RESC0603X03L_C 102.723,43.455 r270 top
R28 "33k" RESC0603X03L_C 25.124,51.461 r180 top
R29 "18k" RESC0603X03L_C 15.879,17.018 r180 top
R30 "18k" RESC0603X03L_C 15.879,16.51 r0 top
R31 "0R" RESC0603X03L_C 25.124,52.486 r0 top
R32 "0R" RESC0603X03L_C 25.424,53.361 r270 top
R33 "0R" RESC1005X04L 90.974,36.755 r180 top
R34 "0R" RESC1005X04L 90.974,35.83 r180 top
R35 "0R" RESC0603X03L_C 26.399,52.486 r0 top
R36 "1k" RESC0603X03L_C 10.799,52.011 r270 top
R37 "150R" RESC0603X03L_C 48.55,11.075 r0 top
R38 "150R" RESC0603X03L_C 48.55,8.784 r0 top
R54 "0R" RESC0603X03L_C 21.449,41.911 r180 top
R55 "100k" RESC0603X03L_C 32.516,25.908 r180 top
R56 "100k" RESC0603X03L_C 32.516,25.273 r180 top
SB1 "Solderbridge" Solderbridge 52.205,6.45 r180 top
SB2 "Solderbridge" Solderbridge_Shorted 12.45,11.089 r0 top net-tie
SB3 "Solderbridge" Solderbridge_SHORTED_0.4 89.8,39.893 r180 top net-tie
SB4 "Solderbridge" Solderbridge_SHORTED_0.4 89.8,38.267 r180 top net-tie
SB5 "Solderbridge" Solderbridge_0.4 91.324,39.893 r90 top
SB6 "Solderbridge" Solderbridge_0.4 91.324,38.267 r270 top
SB8 "Solderbridge" Solderbridge 12.45,12.635 r0 top
SB9 "Solderbridge" Solderbridge_Shorted 86.405,23.648 r90 top net-tie
SB10 "Solderbridge" Solderbridge 87.793,23.638 r90 top
SB11 "Solderbridge" Solderbridge_SHORTED_0.4 96.516,24.531 r180 top net-tie
SB12 "Solderbridge" Solderbridge_SHORTED_0.4 87.041,27.446 r0 top net-tie
SB13 "Solderbridge" Solderbridge_SHORTED_0.4 87.041,28.996 r0 top net-tie
SB14 "Solderbridge" Solderbridge_SHORTED_0.4 96.516,26.096 r180 top net-tie
SB15 "Solderbridge" Solderbridge_SHORTED_0.4 96.516,27.65 r180 top net-tie
SB16 "Solderbridge" Solderbridge_SHORTED_0.4 87.041,25.896 r0 top net-tie
SB17 "Solderbridge" Solderbridge_0.4 84.652,25.884 r0 top
SB18 "Solderbridge" Solderbridge_0.4 84.652,27.453 r0 top
SB19 "Solderbridge" Solderbridge_0.4 84.652,28.996 r0 top
SB20 "Solderbridge" Solderbridge_0.4 98.978,27.65 r180 top
SB21 "Solderbridge" Solderbridge_0.4 98.978,26.096 r180 top
SB22 "Solderbridge" Solderbridge_0.4 98.978,24.531 r180 top
SB24 "Solderbridge" Solderbridge_SHORTED_0.4 55.379,9.998 r0 top net-tie
SW1 "PB SW" Switch-PB-6.2x6.3mm-SMD 5.338,14.097 r180 top
SW2 "PB SW" Switch-PB-6.2x6.3mm-SMD 87.918,14.058 r180 top locked
SW3 "PB SW" Switch-PB-6.2x6.3mm-SMD 98.179,14.058 r180 top locked
SW4 "MK-22D14-G2" MK-22D14-G2 4.521,57.988 r270 top locked
SW5 "PB SW" Switch-PB-6.2x6.3mm-SMD 87.918,4.558 r180 top locked
SW6 "PB SW" Switch-PB-6.2x6.3mm-SMD 98.179,4.558 r180 top locked
TP1 "Ø1.5mm,SMD" TP_SMD_D1.5mm#1 38.104,47.219 r90 bottom locked
TP2 "Ø1.5mm,SMD" TP_SMD_D1.5mm#1 100.339,40.093 r180 bottom locked
TP3 "Ø1.5mm,SMD" TP_SMD_D1.5mm#2 29.62,4.115 r180 bottom locked
TP4 "Ø1.5mm,SMD" TP_SMD_D1.5mm#2 20.616,4.115 r180 bottom locked
TP5 "Ø1.5mm,SMD" TP_SMD_D1.5mm#2 23.616,4.115 r180 bottom locked
TP6 "Ø1.5mm,SMD" TP_SMD_D1.5mm#2 26.616,4.115 r180 bottom locked
TP7 "Ø1.5mm,SMD" TP_SMD_D1.5mm#1 16.004,2 r90 bottom locked
TP8 "Ø1.5mm,SMD" TP_SMD_D1.5mm#1 23.372,58.039 r270 bottom locked
TP9 "Ø1.5mm,SMD" TP_SMD_D1.5mm#1 26.877,54.915 r270 bottom locked
TP10 "Ø1.5mm,SMD" TP_SMD_D1.5mm#1 26.334,48.26 r180 bottom locked
TP11 "Ø1.5mm,SMD" TP_SMD_D1.5mm#1 18.622,57.582 r0 bottom locked
TP12 "Ø1.5mm,SMD" TP_SMD_D1.5mm#1 10.693,48.92 r90 bottom locked
TP13 "Ø1.5mm,SMD" TP_SMD_D1.5mm#1 45.496,13.056 r90 bottom locked
TP14 "Ø1.5mm,SMD" TP_SMD_D1.5mm#1 9.25,31.75 r90 bottom locked
TP15 "Ø1.5mm,SMD" TP_SMD_D1.5mm#1 36.174,49.2 r90 bottom locked
TP16 "Ø1.5mm,SMD" TP_SMD_D1.5mm#1 13.263,23.571 r180 bottom locked
TP17 "Ø1.5mm,SMD" TP_SMD_D1.5mm#1 10.24,26.115 r180 bottom locked
TP18 "Ø1.5mm,SMD" TP_SMD_D1.5mm#1 10.24,23.113 r180 bottom locked
TP22 "TP" S1751 37.323,4.494 r270 top locked
U1 "nRF54L15-QFAAC00" QFN40P600X600X90-48N 98.605,35.53 r0 top locked
U2 "nRF5340-QKAA" AQFN40P700X700X85_HS-99N 22.26,15.864 r0 top locked
U3 "TLV271" SOT95P280X145-5N 22.599,52.486 r90 top locked
U4 "FSA2466UMX" XQFN40P180X260X50-16N 47.76,44.371 r0 top
U5 "FSA2466UMX" XQFN40P180X260X50-16N 47.764,31.536 r0 top
U6 "FSA2466UMX" XQFN40P180X260X50-16N 52.204,9.8 r0 top locked
U7 "TXB0302" XFDFN40P180X120X40-8M 22.195,24.974 r90 top locked
U8 "TXB0302" XFDFN40P180X120X40-8M 25.878,24.974 r90 top locked
U9 "MX25R6435F" SON127P600X80_HS-9N 91.766,26.971 r180 top locked
U10 "nPM1300-QEAAC0" Nordic_QFN50P500X500X90-33N 20.442,45.846 r180 top locked
U11 "ECMF02-4CMX8" UFDFN50P120X250X55-8N 11.079,24.633 r0 top
X1 "32.768kHz" XTAL_2012 88.081,39.074 r90 top
X2 "32MHz" BT-XTAL_2016 103.993,39.234 r90 top
X3 "32MHz" BT-XTAL_2016 29.106,19.719 r90 top locked

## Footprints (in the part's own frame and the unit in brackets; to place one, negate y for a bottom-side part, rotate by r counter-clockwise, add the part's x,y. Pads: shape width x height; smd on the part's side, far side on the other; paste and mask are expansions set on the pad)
"2 PIN STARPOINT" [mil]
  round 6 smd paste-196.85 mask-196.85: 1(8,0) 2(-8,0)
  Top Layer region: -8,-3 8,-3 8,3 -8,3
"2 pin starpoint 20mil" [mil]
  round 20 smd paste-196.85 mask-196.85: 1(15,0) 2(-15,0)
  Top Layer region: -15,10 15,10 15,-10 -15,-10
AQFN40P700X700X85_HS-99N [mm] "AQFN, 98-Leads, Body 7.00x7.00mm, Pitch 0.40mm, Thermal Pad 5.4x5.0mm, IPC Medium Density"
  rect 5.4x5 smd paste-5: 104(0.2,0)
  round 0.4 smd paste+0.012: A1(-3.2,3.2) A31(3.2,3.2) AL1(-3.2,-3.2) AL31(3.2,-3.2)
  round 0.225 smd paste+0.012: A5(-2.2,3.2) A13(-0.6,3.2) A15(-0.2,3.2) A17(0.2,3.2) A19(0.6,3.2) A21(1,3.2) A23(1.4,3.2) A25(1.8,3.2) A27(2.2,3.2) AA1(-3.2,-1) AA31(3.2,-1) AB2(-2.8,-1.2) AC1(-3.2,-1.4) AC31(3.2,-1.4) AD2(-2.8,-1.6) AE1(-3.2,-1.8) AE31(3.2,-1.8) AF2(-2.8,-2) AG1(-3.2,-2.2) AG31(3.2,-2.2) AH2(-2.8,-2.4) AJ1(-3.2,-2.6) AJ31(3.2,-2.6) AK2(-2.8,-2.8) AK4(-2.4,-2.8) AK6(-2,-2.8) AK8(-1.6,-2.8) AK10(-1.2,-2.8) AK12(-0.8,-2.8) AK14(-0.4,-2.8) AK16(0,-2.8) AK18(0.4,-2.8) AK20(0.8,-2.8) AK22(1.2,-2.8) AK24(1.6,-2.8) AK26(2,-2.8) AK28(2.4,-2.8) AK30(2.8,-2.8) AL3(-2.6,-3.2) AL5(-2.2,-3.2) AL7(-1.8,-3.2) AL9(-1.4,-3.2) AL11(-1,-3.2) AL13(-0.6,-3.2) AL15(-0.2,-3.2) AL17(0.2,-3.2) AL19(0.6,-3.2) AL21(1,-3.2) AL23(1.4,-3.2) AL25(1.8,-3.2) AL27(2.2,-3.2) AL29(2.6,-3.2) B2(-2.8,2.8) B4(-2.4,2.8) B6(-2,2.8) B8(-1.6,2.8) B10(-1.2,2.8) B12(-0.8,2.8) B14(-0.4,2.8) B16(0,2.8) B18(0.4,2.8) B20(0.8,2.8) B22(1.2,2.8) B24(1.6,2.8) B26(2,2.8) B28(2.4,2.8) B30(2.8,2.8) C1(-3.2,2.6) C31(3.2,2.6) D2(-2.8,2.4) E1(-3.2,2.2) E31(3.2,2.2) F2(-2.8,2) G1(-3.2,1.8) G31(3.2,1.8) H2(-2.8,1.6) J1(-3.2,1.4) J31(3.2,1.4) K2(-2.8,1.2) L1(-3.2,1) L31(3.2,1) M2(-2.8,0.8) N1(-3.2,0.6) N31(3.2,0.6) P2(-2.8,0.4) R1(-3.2,0.2) R31(3.2,0.2) T2(-2.8,0) U1(-3.2,-0.2) U31(3.2,-0.2) V2(-2.8,-0.4) W1(-3.2,-0.6) W31(3.2,-0.6) Y2(-2.8,-0.8)
  rrect15% 1.1x1 on Top Paste: ""(-1.75,-1.8) ""(-1.75,-0.6) ""(-1.75,0.6) ""(-1.75,1.8) ""(-0.45,-1.8) ""(-0.45,-0.6) ""(-0.45,0.6) ""(-0.45,1.8) ""(0.85,-1.8) ""(0.85,-0.6) ""(0.85,0.6) ""(0.85,1.8) ""(2.15,-1.8) ""(2.15,-0.6) ""(2.15,0.6) ""(2.15,1.8)
  silkscreen extent -4.22,3.23 -3.97,3.47, body extent -3.5,-3.5 3.5,3.5, height 0.85
BT-XTAL_2016 [mm] "Crystal 2.0 x 1.6 mm"
  rect 0.95x0.85 smd: 1(-0.725,-0.575) 2(0.725,-0.575) 3(0.725,0.575) 4(-0.725,0.575)
  silkscreen extent -0.1,-0.88 0.1,0.88, body extent -1.05,-0.85 1.05,0.85, height 0.56
CAPC0603X03L_C [mm] "Chip Capacitor, 2-Leads, Body 0.6x0.3mm, IPC High Density"
  rect 0.27x0.3 smd mask+0.05: 1(-0.285,0) 2(0.285,0)
  body extent -0.3,-0.15 0.3,0.15, height 0.3
CAPC1005X04L [mm] "Chip Capacitor, 2-Leads, Body 1.0x0.5mm, IPC High Density"
  rect 0.6x0.5 smd: 1(-0.5,0) 2(0.5,0)
  body extent -0.5,-0.25 0.5,0.25, height 0.5
CAPC1608X06L [mm] "Chip Capacitor, 2-Leads, Body 1.6x0.8mm, IPC High Density"
  rect 0.75x0.8 smd: 1(-0.675,0) 2(0.675,0)
  silkscreen extent -1.17,-0.5 1.17,0.5, body extent -0.8,-0.4 0.8,0.4, height 0.8
COAXIAL-SWF [mm]
  rect 0.5x0.58 smd: 1(0,1.16) 3(0,-1.16)
  rect 0.75x0.8 smd: 2(-1.025,-0.95) 2(-1.025,0.95) 2(1.025,-0.95) 2(1.025,0.95)
  Top Layer pour cut-out: 0.65,-0.55 -0.65,-0.55 -0.65,-1.35 0.65,-1.35
  Top Layer pour cut-out: -0.65,0.55 0.65,0.55 0.65,1.35 -0.65,1.35
  silkscreen extent -1.25,-1.25 1.25,1.25, body extent -1.26,-1.3 1.26,1.3, height 1.55
DFN105P200X65-3N_v2 [mm] "DFN, 3-Leads, Body 2.00x2.00mm, Pitch 1.05mm, IPC Medium Density"
  rect 0.5x0.4 smd: 1(-0.8,0.65) 2(-0.8,-0.65)
  rect 1.1x1.6 smd: 3(0.25,0)
  Top Layer region: 0.65,-0.2 1.05,-0.2 1.05,0.2 0.65,0.2
  silkscreen extent -1.2,-1.06 1.06,1.36, body extent -1,-1 1,1, height 0.65
Fiducial [mm] "Fiducial Mark"
  round 1 smd paste-2539.97 mask+0.5: 0(0,0)
  round 1 smd far side paste-2539.97 mask+0.5: 0(0,0)
  Top Layer keep-out circle w0.01: c0,0 r1
  Bottom Layer keep-out circle w0.01: c0,0 r1
FPC_05P-0.5mm-RA-SMD [mm] "FPC, 5-Leads, Pitch 0,5mm"
  rect 0.6x2.6 smd: 0(-0.9,-2.3) 0(2.9,-2.3)
  rect 0.3x0.8 smd mask+0.05: 1(0,0) 2(0.5,0) 3(1,0) 4(1.5,0) 5(2,0)
  silkscreen extent -1.38,-3.93 3.38,0.08, body extent -1.3,-3.85 3.3,0.2, height 1.2
HDR_2x2-SMD [mil] "Board-Board Conn, Header, 4-way, 2-row"
  rect 40x113 smd: 1(-50,-100) 2(-50,100) 3(50,-100) 4(50,100)
  silkscreen extent -105,-135 100,100, body extent -100,-148 100,148, height 382
HDR_2x5-SMD-1.27mm-K [mm] "SMT MICRO HEADER, (1,27) .050\" Keying Shroud"
  rect 0.76x2.4 smd: 1(-2.54,-1.95) 2(-2.54,1.95) 3(-1.27,-1.95) 4(-1.27,1.95) 5(0,-1.95) 6(0,1.95) 7(1.27,-1.95) 8(1.27,1.95) 9(2.54,-1.95) 10(2.54,1.95)
  silkscreen extent -3.56,-2.38 3.25,1.75, body extent -3.14,-2.92 3.14,2.92, height 6.11
HDR_2x10-SMD [mil] "Board-Board Conn, Header, 20-way, 2-row"
  rect 40x113 smd: 1(-450,-100) 2(-450,100) 3(-350,-100) 4(-350,100) 5(-250,-100) 6(-250,100) 7(-150,-100) 8(-150,100) 9(-50,-100) 10(-50,100) 11(50,-100) 12(50,100) 13(150,-100) 14(150,100) 15(250,-100) 16(250,100) 17(350,-100) 18(350,100) 19(450,-100) 20(450,100)
  silkscreen extent -505,-135 500,100, body extent -500,-148 500,148, height 382
HDR_2x10-SMD-1.27mm-NC [mm] "SMT MICRO HEADER, (1,27) .050\""
  rect 0.76x2.4 smd: 1(-5.715,-1.95) 2(-5.715,1.95) 3(-4.445,-1.95) 4(-4.445,1.95) 5(-3.175,-1.95) 6(-3.175,1.95) 7(-1.905,-1.95) 8(-1.905,1.95) 9(-0.635,-1.95) 10(-0.635,1.95) 11(0.635,-1.95) 12(0.635,1.95) 13(1.905,-1.95) 14(1.905,1.95) 15(3.175,-1.95) 16(3.175,1.95) 17(4.445,-1.95) 18(4.445,1.95) 19(5.715,-1.95) 20(5.715,1.95)
  silkscreen extent -6.73,-2.38 6.43,1.75
INDC0603X03L_C [mm] "Chip Inductor, 2-Leads, Body 0.6x0.3mm, IPC High Density"
  rect 0.27x0.3 smd: 1(-0.285,0) 2(0.285,0)
  body extent -0.3,-0.15 0.3,0.15, height 0.3
INDC1005X04L [mm] "Chip Inductor, 2-Leads, Body 1.0x0.5mm, IPC High Density"
  rect 0.65x0.5 smd: 1(-0.475,0) 2(0.475,0)
  body extent -0.5,-0.25 0.5,0.25, height 0.5
INDC1608X06L [mm] "Chip Inductor, 2-Leads, Body 1.6x0.8mm, IPC High Density"
  rect 0.75x0.8 smd: 1(-0.675,0) 2(0.675,0)
  silkscreen extent -0.1,-0.3 0.1,0.3, body extent -0.8,-0.4 0.8,0.4, height 0.8
INDC2016X10N [mm] "Chip Inductor, 2-Leads, Body 2.00x1.60mm, IPC Medium Density"
  rect 1.13x1.82 smd: 1(-0.885,0) 2(0.885,0)
  silkscreen extent -1.65,-1.14 1.65,1.14, body extent -1,-0.8 1,0.8, height 1
LabelSilk_12x12 [mm] "PCA version label, stick-on, 12x12mm"
  silkscreen extent 0,0 12,12, body extent 0,0 12,12, height 0.05
LED_0603_G [mil] "SMD Super Bright LED, GREEN"
  rect 30x32 smd: 1(-27.5,0) 2(27.5,0)
  silkscreen extent -58,-20 -48,19, body extent -32,-16 32,16, height 24
LIST_1x3 [mm] "Pin List, 2.54mm through hole"
  rect 1.5x1.5 hole 0.9: 1(-2.54,0)
  round 1.5 hole 0.9: 2(0,0) 3(2.54,0)
  body extent -3.81,-1.27 3.71,1.23, height 8.2
LIST_1x3_SMD [mm] "Pin List, 2.54mm, SMD"
  rect 1.02x2.19 smd: 1(0,1.465) 1(0,-1.465) 2(2.54,-1.465) 2(2.54,1.465) 3(5.08,-1.465) 3(5.08,1.465)
  silkscreen extent -1.27,-1.27 6.35,1.27, body extent -1.27,-2.5 6.35,2.5, height 9.82
MK-22D14-G2 [mm] "Slide Switches - DPDT, SMD, ON-ON"
  rect 1x1.5 smd: 1(2.5,-3.5) 2(0,-3.5) 3(-2.5,-3.5) 4(2.5,3.5) 5(0,3.5) 6(-2.5,3.5)
  silkscreen extent -4.5,-3.75 4.5,1.88, body extent -4.5,-3.72 4.5,3.78, height 3.47
NORDIC_LOGO_LYING [mm]
  silkscreen extent -2.57,-2.24 13.7,2.24
Nordic_QFN50P500X500X90-33N [mm] "QFN32 5x5x0.85mm, 0.5mm pitch - Medium Density"
  oval 0.85x0.3 smd: 1(-2.45,1.75) 2(-2.45,1.25) 3(-2.45,0.75) 4(-2.45,0.25) 5(-2.45,-0.25) 6(-2.45,-0.75) 7(-2.45,-1.25) 8(-2.45,-1.75) 17(2.45,-1.75) 18(2.45,-1.25) 19(2.45,-0.75) 20(2.45,-0.25) 21(2.45,0.25) 22(2.45,0.75) 23(2.45,1.25) 24(2.45,1.75)
  oval 0.3x0.85 smd: 9(-1.75,-2.45) 10(-1.25,-2.45) 11(-0.75,-2.45) 12(-0.25,-2.45) 13(0.25,-2.45) 14(0.75,-2.45) 15(1.25,-2.45) 16(1.75,-2.45) 25(1.75,2.45) 26(1.25,2.45) 27(0.75,2.45) 28(0.25,2.45) 29(-0.25,2.45) 30(-0.75,2.45) 31(-1.25,2.45) 32(-1.75,2.45)
  rect 3.5x3.5 smd: 33(0,0)
  silkscreen extent -3.43,-2.57 2.57,2.62, body extent -2.5,-2.5 2.5,2.5, height 0.9
QFN40P600X600X90-48N [mm] "QFN, 48-Leads, Body 6,0x6,0mm (max), Pitch 0,40mm, IPC Medium Density"
  oval 0.65x0.2 smd mask+0.05: 1(-3.025,2.2) 2(-3.025,1.8) 3(-3.025,1.4) 4(-3.025,1) 5(-3.025,0.6) 6(-3.025,0.2) 7(-3.025,-0.2) 8(-3.025,-0.6) 9(-3.025,-1) 10(-3.025,-1.4) 11(-3.025,-1.8) 12(-3.025,-2.2) 25(3.025,-2.2) 26(3.025,-1.8) 27(3.025,-1.4) 28(3.025,-1) 29(3.025,-0.6) 30(3.025,-0.2) 31(3.025,0.2) 32(3.025,0.6) 33(3.025,1) 34(3.025,1.4) 35(3.025,1.8) 36(3.025,2.2)
  oval 0.2x0.65 smd mask+0.05: 13(-2.2,-3.025) 14(-1.8,-3.025) 15(-1.4,-3.025) 16(-1,-3.025) 17(-0.6,-3.025) 18(-0.2,-3.025) 19(0.2,-3.025) 20(0.6,-3.025) 21(1,-3.025) 22(1.4,-3.025) 23(1.8,-3.025) 24(2.2,-3.025) 37(2.2,3.025) 38(1.8,3.025) 39(1.4,3.025) 40(1,3.025) 41(0.6,3.025) 42(0.2,3.025) 43(-0.2,3.025) 44(-0.6,3.025) 45(-1,3.025) 46(-1.4,3.025) 47(-1.8,3.025) 48(-2.2,3.025)
  rect 4.7x4.7 smd: 49(0,0)
  silkscreen extent -4.02,-3 3,3, body extent -3.02,-3.02 3.02,3.02, height 0.86
RESC0603X03L_C [mm] "Chip Resistor, 2-Leads, Body 0.6x0.3mm, IPC High Density"
  rect 0.27x0.3 smd: 1(-0.285,0) 2(0.285,0)
  body extent -0.3,-0.15 0.3,0.15, height 0.23
RESC1005X04L [mm] "Chip Resistor, 2-Leads, Body 1.0x0.5mm, IPC High Density"
  rect 0.6x0.55 smd mask+0.05: 1(-0.5,0) 2(0.5,0)
  body extent -0.5,-0.25 0.5,0.25, height 0.3
S1751 [mm]
  rect 3.45x1.85 smd: 1(0,0)
  silkscreen extent -2.04,-1.25 2.06,1.25, body extent -1.67,-0.8 1.58,0.85, height 2.05
SD-80259-001 [mm] "USB TYPE C RECEPTACLE, 16 PIN"
  round 0.6 hole 0.6 unplated: 0(-2.89,1.315) 0(2.89,1.315)
  rect 0.6x1.14 smd: A1(-3.2,2.385) A4(-2.4,2.385) A9(2.4,2.385) A12(3.2,2.385)
  rect 0.3x1.14 smd: A5(-1.25,2.385) A6(-0.25,2.385) A7(0.25,2.385) A8(1.25,2.385) B5(1.75,2.385) B6(0.75,2.385) B7(-0.75,2.385) B8(-1.75,2.385)
  oval 0.9x2 hole 0.6 slot 1.7 at 90 deg: SHLD(-4.325,1.795) SHLD(4.325,1.795)
  oval 0.9x1.7 hole 0.6 slot 1.4 at 90 deg: SHLD(-4.325,-2.385) SHLD(4.325,-2.385)
  oval 0.9x2 on Top Paste: ""(-4.32,1.795) ""(4.32,1.795)
  oval 0.9x1.7 on Top Paste: ""(-4.32,-2.385) ""(4.32,-2.385)
  silkscreen extent -4.33,-4.48 4.33,0.47, body extent -4.48,-4.98 4.48,2.74, height 3.26
SEGGER_LOGO_S [mm] "Logo 7.82 mm x 3.84 mm, print overlay"
  silkscreen extent -3.91,-1.92 3.91,1.92
Shunt_2.54mm_Vertical [mm]
  body extent -2.51,-1.24 2.51,1.24, height 9
Solderbridge [mil]
  round 1 smd paste-99999: 1(-13.78,0) 2(13.78,0)
  Top Layer region: 7.49,-19.36 15.76,-15.74 21.55,-8.8 23.62,0 23.62,0 21.55,8.79 15.76,15.74 7.49,19.36 7.49,19.36 6.18,19.31 5.02,18.71 4.22,17.68 3.94,16.4 3.94,16.4 3.94,-16.4 4.22,-17.68 5.02,-18.71 6.18,-19.31 7.49,-19.36
  Top Layer region: -7.49,19.36 -15.76,15.74 -21.55,8.8 -23.62,0 -23.62,0 -21.55,-8.79 -15.76,-15.74 -7.49,-19.36 -7.49,-19.36 -6.18,-19.31 -5.02,-18.71 -4.22,-17.68 -3.94,-16.4 -3.94,-16.4 -3.94,16.4 -4.22,17.68 -5.02,18.71 -6.18,19.31 -7.49,19.36
Solderbridge_0.4 [mm]
  round 0.2 smd paste-10: 1(-0.312,0) 2(0.312,0)
  Top Layer region: 0.077,0.553 0.203,0.512 0.335,0.424 0.409,0.351 0.462,0.292 0.521,0.193 0.549,0.099 0.544,-0.122 0.518,-0.193 0.434,-0.33 0.351,-0.411 0.152,-0.536 0.077,-0.559
  Top Layer region: -0.077,-0.553 -0.129,-0.605 -0.205,-0.554 -0.409,-0.351 -0.462,-0.292 -0.521,-0.193 -0.549,-0.099 -0.544,0.122 -0.518,0.193 -0.434,0.33 -0.351,0.411 -0.259,0.469 -0.159,0.556 -0.08,0.565
  Top Layer lines w0.152: -0.156,0.557 ccw(c-0.035,0) -0.153,-0.558 ; 0.153,0.557 cw(c0.03,0) 0.153,-0.557
Solderbridge_Shorted [mil]
  round 1 smd paste-99999: 1(-13.78,0) 2(13.78,0)
  Top Layer region: -4.92,3.94 -4.92,-3.94 4.92,-3.94 4.92,3.94
  Top Layer region: -7.49,19.36 -15.76,15.74 -21.55,8.8 -23.62,0 -23.62,0 -21.55,-8.79 -15.76,-15.74 -7.49,-19.36 -7.49,-19.36 -6.18,-19.31 -5.02,-18.71 -4.22,-17.68 -3.94,-16.4 -3.94,-16.4 -3.94,16.4 -4.22,17.68 -5.02,18.71 -6.18,19.31 -7.49,19.36
  Top Layer region: 7.49,-19.36 15.76,-15.74 21.55,-8.8 23.62,0 23.62,0 21.55,8.79 15.76,15.74 7.49,19.36 7.49,19.36 6.18,19.31 5.02,18.71 4.22,17.68 3.94,16.4 3.94,16.4 3.94,-16.4 4.22,-17.68 5.02,-18.71 6.18,-19.31 7.49,-19.36
Solderbridge_SHORTED_0.4 [mm]
  round 0.2 smd paste-10: 1(-0.312,0) 2(0.312,0)
  Top Layer region: -0.077,-0.553 -0.129,-0.605 -0.205,-0.554 -0.409,-0.351 -0.462,-0.292 -0.521,-0.193 -0.549,-0.099 -0.544,0.122 -0.518,0.193 -0.434,0.33 -0.351,0.411 -0.259,0.469 -0.159,0.556 -0.08,0.565
  Top Layer region: 0.077,0.553 0.203,0.512 0.335,0.424 0.409,0.351 0.462,0.292 0.521,0.193 0.549,0.099 0.544,-0.122 0.518,-0.193 0.434,-0.33 0.351,-0.411 0.152,-0.536 0.077,-0.559
  Top Layer lines w0.152: 0.153,0.557 cw(c0.03,0) 0.153,-0.557 ; -0.153,-0.558 cw(c-0.035,0) -0.156,0.557
  Top Layer lines w0.203: 0.363,0 -0.312,0
SON127P600X80_HS-9N [mm] "SON, 8-Leads, Body 5.00x6.00mm, Pitch 1.27mm, Thermal Pad 4.00x3.40mm, IPC Medium Density"
  rect 1.15x0.45 smd: 1(-2.77,1.905) 2(-2.77,0.635) 3(-2.77,-0.635) 4(-2.77,-1.905) 5(2.77,-1.905) 6(2.77,-0.635) 7(2.77,0.635) 8(2.77,1.905)
  rect 3.4x4 smd paste-1.7: 9(0,0)
  silkscreen extent -3.98,-2.6 3.1,2.67, body extent -3.05,-2.55 3.05,2.55, height 0.8
SOT95P280X145-5N [mm] "SOT23, 5-Leads, Body 2,90x2,80mm, Pitch 0,95mm, IPC Medium Density"
  rect 1x0.6 smd: 1(-1.35,0.95) 2(-1.35,0) 3(-1.35,-0.95) 4(1.35,-0.95) 5(1.35,0.95)
  silkscreen extent -1.47,-1.5 0.45,1.92, body extent -1.5,-1.55 1.5,1.55, height 1.45
Switch-PB-6.2x6.3mm-SMD [mm] "6.2×6.5mm TACT Switch, without ground connector"
  rect 2.75x1.4 smd: 1(-3.375,2) 1(3.375,2) 2(-3.375,-2) 2(3.375,-2)
  silkscreen extent -3,-3 3,3, body extent -3.6,-3.1 3.6,3.1, height 2.5
TC2050-IDC-NLFP [mil]
  round 39 hole 39 unplated mask+0.79: 0(-150,0) 0(150,-40) 0(150,40)
  round 31 smd paste-196.85: 1(-100,-25) 2(-50,-25) 3(0,-25) 4(50,-25) 5(100,-25) 6(100,25) 7(50,25) 8(0,25) 9(-50,25) 10(-100,25)
  Top Layer pour cut-out: -100,25 -100,-25 100,-25 100,25
TP_SMD_D1.5mm#1 [mm] "Test point - pad 1.5mm"
  round 1.5 smd paste-5: 1(0,0)
  body extent -0.75,-0.75 0.75,0.75, height 0.05
TP_SMD_D1.5mm#2 [mm] "Test point - pad 1.5mm"
  round 1.5 smd paste-5: 1(0,0.01)
  body extent -0.75,-0.75 0.75,0.75, height 0.05
TSSOP6 [mm] "TSSOP6 (SOT-363)"
  rect 0.6x0.6 smd: 1(-0.75,-0.9) 3(0.75,-0.9) 4(0.75,0.9) 6(-0.75,0.9)
  rect 0.4x0.6 smd: 2(0,-0.9) 5(0,0.9)
  silkscreen extent -1.47,-1.07 1,0.45, body extent -1,-1.05 1,1.05, height 0.93
UFDFN50P120X250X55-8N [mm]
  round 0.025 smd: 1(-0.5,0.75) 4(-0.5,-0.75) 5(0.5,-0.75) 8(0.5,0.75)
  rect 0.6x0.2 smd: 2(-0.5,0.25) 3(-0.5,-0.25) 6(0.5,-0.25) 7(0.5,0.25)
  Top Layer region: -0.2,0.65 -0.8,0.65 -0.8,0.85 -0.4,0.85 -0.4,1.05 -0.2,1.05
  Top Layer region: 0.4,0.85 0.8,0.85 0.8,0.65 0.2,0.65 0.2,1.05 0.4,1.05
  Top Layer region: -0.2,-1.05 -0.4,-1.05 -0.4,-0.85 -0.8,-0.85 -0.8,-0.65 -0.2,-0.65
  Top Layer region: 0.8,-0.85 0.4,-0.85 0.4,-1.05 0.2,-1.05 0.2,-0.65 0.8,-0.65
  silkscreen extent -1.08,-1.37 0.6,1.37, body extent -0.6,-1.25 0.6,1.25, height 0.6
WEE_3x4.5mm [mm]
  silkscreen extent -1.47,-2.7 1.47,1.71
XFDFN40P180X120X40-8M [mm] "QFN, 8-Leads, Body 1.80x1.20mm, Pitch 0.40mm, IPC Low Density"
  oval 0.85x0.25 smd: 1(-0.625,0.6) 2(-0.625,0.2) 3(-0.625,-0.2) 4(-0.625,-0.6) 5(0.625,-0.6) 6(0.625,-0.2) 7(0.625,0.2) 8(0.625,0.6)
  silkscreen extent -1.02,-0.92 0.63,1.32, body extent -0.63,-0.92 0.63,0.92, height 0.4
XQFN40P180X260X50-16N [mm] "QFN, 16-Leads, Body 1.80x2.60mm, Pitch 0.40mm, IPC Medium Density"
  oval 0.65x0.22 smd paste-0.02 mask+0.04: 1(-0.825,0.6) 2(-0.825,0.2) 3(-0.825,-0.2) 4(-0.825,-0.6) 9(0.825,-0.6) 10(0.825,-0.2) 11(0.825,0.2) 12(0.825,0.6)
  oval 0.22x0.65 smd paste-0.02 mask+0.04: 5(-0.6,-1.225) 6(-0.2,-1.225) 7(0.2,-1.225) 8(0.6,-1.225) 13(0.6,1.225) 14(0.2,1.225) 15(-0.2,1.225) 16(-0.6,1.225)
  silkscreen extent -1.45,-1.4 1,1.4, body extent -0.91,-1.31 0.91,1.31, height 0.55
XTAL_2012 [mm] "XTAL SMD 2.0 x 1.2 mm"
  rect 0.75x1.4 smd: 1(-0.725,0) 2(0.725,0)
  silkscreen extent -0.17,-0.6 0.17,0.6, body extent -1,-0.61 1,0.61, height 0.6

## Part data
C1 C2: library part C0201-2µ2-2.5V-X6T-GRM033D80E225ME47D, "Capacitor, Ceramic, 2.2µF 2.5V X6T 0201,±20%", Manufacturer=Murata, Manufacturer Part Number=GRM033R61A225KE47, Part number IPS=N.A., Part number NEMS=100200527, Supplier Part Number 1=81-GRM033D80E225ME7D
C3 C10: library part C0402-10µF-6.3V-X6S, "Capacitor, X6S, ±20%, 6.3V", Manufacturer=N.A., Part number NEMS=100200478
C4 C7 C8 C11 C13 C14 C15 C16 C18 C20 C21 C22 C29 C34 C35 C36 C37 C44 C46 C48 C49 C52 C53 C55 C56 C57: library part C0201-100n, "Capacitor, X5R, ±10%", Manufacturer=N.A., Part number IPS="00000001248, 00000002505", Part number NEMS=100200078, Part number Norautron=262071862
C5 C33: library part C0201-2n2, "Capacitor, X7R, ±10%, 10V", Manufacturer=N.A., Part number IPS=00000001778, Part number NEMS=100200060, Part number Norautron=26470002
C6: library part C0201-1.5p-25V-NP0-GJM0335C1E1R5WB01, "Capacitor, NP0, ±0.05pF, 25V, High Q", Manufacturer=Murata, Manufacturer Part Number=GJM0335C1E1R5WB01, Part number IPS=N.A., Part number NEMS=100200477, Supplier Part Number 1=490-11176-2-ND
C9: library part C0201-2.0p-HQ-Murata, "Capacitor, NP0, ±0.05pF, 25V", Manufacturer=Murata, Manufacturer Part Number=GJM0335C1E2R0WB01, Part number IPS=00000001775, Part number NEMS=100200419, Part number Norautron=N.A.
C12 C30 C50: library part C0201-10n, "Capacitor, X7R, ±10%", Manufacturer=N.A., Part number IPS=00000003480, Part number NEMS=100200067, Part number Norautron=26621779
C17 C19: library part C0402-300p, "Capacitor, C0G, ±5%, 50V", Manufacturer=N.A., Part number IPS=00000007788, Part number NEMS=100200155, Supplier Part Number 1=490-3234-1-ND
C23: library part C0402-2µ2-10V, "Capacitor, X5R, ±10%", Manufacturer=N.A., Part number NEMS=100200376, Supplier Part Number 1=490-10451-1-ND
C24 C25 C26 C27 C28: library part C0603-10µ-10V-X7T-GRM188D71A106MA73, "Capacitor, X7T, ±20%, 10V", Manufacturer=Murata, Manufacturer Part Number=GRM188D71A106MA73, Part number IPS=00000004696, Part number NEMS=100200414, Part number Norautron=N.A., Supplier Part Number 1=490-7200-1-ND
C31 C32 C38 C39 C45: library part C0402-1µ0-6.3V-X5R-10%, "Capacitor, X5R, ±10%, 6.3V", Manufacturer=N.A., Part number NEMS=100200498, Part number Norautron=26207137
C40: library part C0201-1.4p-25V-GJM0335C1E1R4WB01D, "Capacitor, C0G, ±0.05pF, 25V", Manufacturer=Murata, Manufacturer Part Number=GJM0335C1E1R4WB01D, Part number IPS=N.A., Part number NEMS=100200553, Supplier Part Number 1=490-GJM0335C1E1R4WB01DTR-ND
C41: library part C0402-100n, "Capacitor, X7R, ±10%", Manufacturer=N.A., Part number IPS=00000005296, Part number NEMS=100200184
